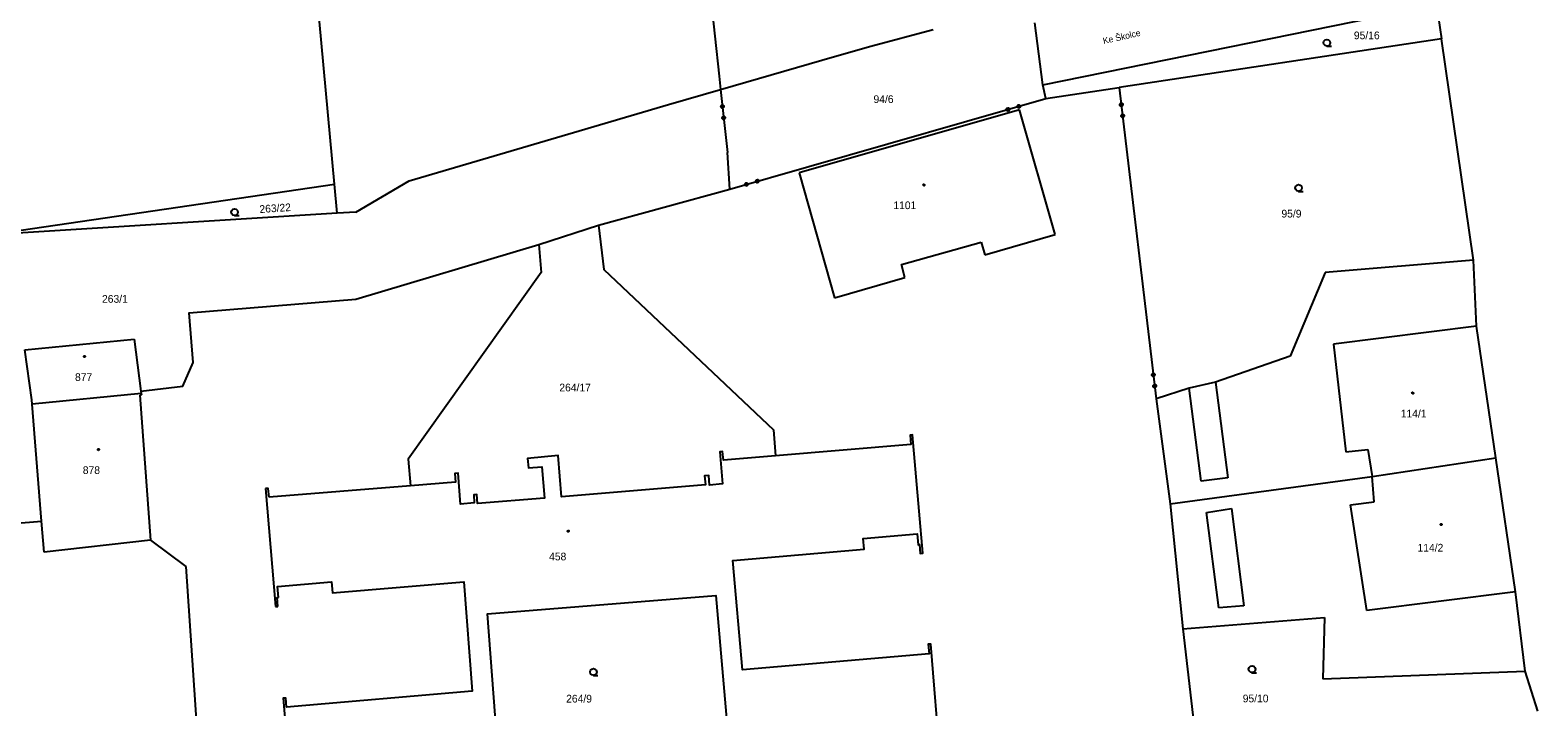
# Model space of a CAD drawing. Extents: x -757994 to -755874, y -1047691 to -1046119.
# Drawn here: x -757261.1 to -757094.8, y -1047292 to -1047217.4 of the extents above; entities that cross this region are included whole.
import ezdxf

# ---------------------------------------------------------------- set-up
doc = ezdxf.new("R2010")
doc.units = 0
doc.layers.add('katastrální mapa', color=7, linetype='Continuous')

msp = doc.modelspace()

# ---------------------------------------------------------------- linework, layer by layer
at = {"layer": 'katastrální mapa'}
for p, q in [((-757227.56, -1047234.43), (-757234.45, -1047159.9)), ((-757190.76, -1047170.38), (-757185.13, -1047222.5)), ((-757149.43, -1047223.45), (-757105.99, -1047214.66)), ((-757105.99, -1047214.66), (-757105.45, -1047218.39)), ((-757168.4, -1047219.21), (-757161.51, -1047217.36)), ((-757149.43, -1047223.45), (-757150.29, -1047216.64)), ((-757172.4, -1047220.36), (-757168.4, -1047219.21)), ((-757105.45, -1047218.39), (-757140.99, -1047223.76)), ((-757101.91, -1047242.8), (-757105.45, -1047218.39)), ((-757184.97, -1047223.97), (-757172.4, -1047220.36)), ((-757185.13, -1047222.5), (-757184.97, -1047223.97)), ((-757190.72, -1047225.62), (-757184.97, -1047223.97)), ((-757184.97, -1047223.97), (-757184.22, -1047230.92)), ((-757149.1, -1047224.98), (-757149.43, -1047223.45)), ((-757149.1, -1047224.98), (-757140.99, -1047223.76)), ((-757140.99, -1047223.76), (-757136.93, -1047258.08)), ((-757201.81, -1047228.89), (-757190.72, -1047225.62)), ((-757183.95, -1047234.96), (-757149.1, -1047224.98)), ((-757151.99, -1047226.23), (-757176.31, -1047233.17)), ((-757148.05, -1047239.97), (-757151.99, -1047226.23)), ((-757219.33, -1047234.05), (-757201.81, -1047228.89)), ((-757183.95, -1047234.96), (-757184.22, -1047230.92)), ((-757225.19, -1047237.5), (-757219.33, -1047234.05)), ((-757176.31, -1047233.17), (-757172.39, -1047246.93)), ((-757265.74, -1047240.02), (-757227.56, -1047234.43)), ((-757227.26, -1047237.63), (-757227.56, -1047234.43)), ((-757198.44, -1047238.94), (-757183.95, -1047234.96)), ((-757227.26, -1047237.63), (-757265.74, -1047240.02)), ((-757225.19, -1047237.5), (-757227.26, -1047237.63)), ((-757205.02, -1047241.08), (-757198.44, -1047238.94)), ((-757165.03, -1047243.26), (-757156.24, -1047240.8)), ((-757156.24, -1047240.8), (-757155.81, -1047242.21)), ((-757155.81, -1047242.21), (-757148.05, -1047239.97)), ((-757164.63, -1047244.7), (-757165.03, -1047243.26)), ((-757118.27, -1047244.15), (-757122.16, -1047253.39)), ((-757101.91, -1047242.8), (-757118.27, -1047244.15)), ((-757101.58, -1047250.06), (-757101.91, -1047242.8)), ((-757172.39, -1047246.93), (-757164.63, -1047244.7)), ((-757101.58, -1047250.06), (-757117.37, -1047252.05)), ((-757099.46, -1047264.58), (-757101.58, -1047250.06)), ((-757261.69, -1047252.67), (-757249.65, -1047251.49)), ((-757260.92, -1047258.21), (-757261.69, -1047252.67)), ((-757249.65, -1047251.49), (-757248.9, -1047257.23)), ((-757117.37, -1047252.05), (-757116.02, -1047263.94)), ((-757122.16, -1047253.39), (-757130.39, -1047256.24)), ((-757248.87, -1047257.48), (-757260.88, -1047258.66)), ((-757248.84, -1047257.65), (-757249.01, -1047257.68)), ((-757248.9, -1047257.23), (-757248.87, -1047257.48)), ((-757248.87, -1047257.48), (-757248.84, -1047257.65)), ((-757133.28, -1047256.92), (-757136.93, -1047258.08)), ((-757130.39, -1047256.24), (-757133.28, -1047256.92)), ((-757131.98, -1047267.15), (-757133.28, -1047256.92)), ((-757130.39, -1047256.24), (-757129.03, -1047266.78)), ((-757260.88, -1047258.66), (-757260.92, -1047258.21)), ((-757259.88, -1047271.57), (-757260.88, -1047258.66)), ((-757249.01, -1047257.68), (-757247.85, -1047273.65)), ((-757136.93, -1047258.08), (-757135.38, -1047269.65)), ((-757116.02, -1047263.94), (-757113.59, -1047263.68)), ((-757113.59, -1047263.68), (-757113.09, -1047266.64)), ((-757113.09, -1047266.64), (-757099.46, -1047264.58)), ((-757097.28, -1047279.34), (-757099.46, -1047264.58)), ((-757135.38, -1047269.65), (-757113.09, -1047266.64)), ((-757129.03, -1047266.78), (-757131.98, -1047267.15)), ((-757112.89, -1047269.42), (-757113.09, -1047266.64)), ((-757235.17, -1047267.98), (-757234.07, -1047280.98)), ((-757219.18, -1047267.68), (-757234.77, -1047268.94)), ((-757135.38, -1047269.65), (-757133.98, -1047283.45)), ((-757131.38, -1047270.62), (-757128.63, -1047270.17)), ((-757130.02, -1047281.14), (-757131.38, -1047270.62)), ((-757128.63, -1047270.17), (-757127.27, -1047280.89)), ((-757115.48, -1047269.76), (-757112.89, -1047269.42)), ((-757113.68, -1047281.4), (-757115.48, -1047269.76)), ((-757262.98, -1047271.83), (-757259.88, -1047271.57)), ((-757259.57, -1047274.97), (-757259.88, -1047271.57)), ((-757247.85, -1047273.65), (-757259.57, -1047274.97)), ((-757247.85, -1047273.65), (-757243.94, -1047276.55)), ((-757243.94, -1047276.55), (-757242.75, -1047294.55)), ((-757127.27, -1047280.89), (-757130.02, -1047281.14)), ((-757097.28, -1047279.34), (-757113.68, -1047281.4)), ((-757096.23, -1047288.12), (-757097.28, -1047279.34)), ((-757234.07, -1047280.98), (-757233.79, -1047280.96)), ((-757133.98, -1047283.45), (-757118.36, -1047282.19)), ((-757118.36, -1047282.19), (-757118.56, -1047288.96)), ((-757133.98, -1047283.45), (-757132.41, -1047297.02)), ((-757118.56, -1047288.96), (-757096.23, -1047288.12)), ((-757094.83, -1047292.5), (-757096.23, -1047288.12))]:
    msp.add_line(p, q, dxfattribs=at)
for points in [[(-757118.09, -1047219.19), (-757118.28, -1047219.14), (-757118.42, -1047219), (-757118.47, -1047218.82), (-757118.42, -1047218.64), (-757118.28, -1047218.5), (-757118.1, -1047218.45), (-757117.91, -1047218.5), (-757117.77, -1047218.64), (-757117.73, -1047218.83), (-757117.77, -1047219.01), (-757117.91, -1047219.15), (-757118.1, -1047219.2), (-757117.6, -1047219.2)], [(-757184.6, -1047225.91), (-757184.68, -1047226.01), (-757184.82, -1047226.03), (-757184.92, -1047225.94), (-757184.94, -1047225.81), (-757184.85, -1047225.7), (-757184.72, -1047225.69), (-757184.61, -1047225.77), (-757184.6, -1047225.91), (-757184.62, -1047225.9), (-757184.63, -1047225.78), (-757184.68, -1047225.75), (-757184.66, -1047225.95), (-757184.69, -1047225.99), (-757184.72, -1047225.71), (-757184.76, -1047225.72), (-757184.73, -1047226), (-757184.77, -1047226), (-757184.8, -1047225.72), (-757184.84, -1047225.73), (-757184.81, -1047226), (-757184.85, -1047225.97), (-757184.88, -1047225.77), (-757184.91, -1047225.81), (-757184.9, -1047225.93)], [(-757153.26, -1047226.01), (-757153.15, -1047226.07), (-757153.11, -1047226.2), (-757153.17, -1047226.32), (-757153.3, -1047226.36), (-757153.42, -1047226.29), (-757153.46, -1047226.16), (-757153.39, -1047226.04), (-757153.26, -1047226.01), (-757153.26, -1047226.03), (-757153.38, -1047226.06), (-757153.41, -1047226.11), (-757153.21, -1047226.05), (-757153.16, -1047226.08), (-757153.43, -1047226.16), (-757153.42, -1047226.2), (-757153.15, -1047226.12), (-757153.14, -1047226.16), (-757153.41, -1047226.24), (-757153.4, -1047226.27), (-757153.13, -1047226.2), (-757153.16, -1047226.25), (-757153.35, -1047226.3), (-757153.3, -1047226.33), (-757153.19, -1047226.3)], [(-757152.06, -1047225.66), (-757151.95, -1047225.73), (-757151.91, -1047225.86), (-757151.97, -1047225.97), (-757152.1, -1047226.01), (-757152.22, -1047225.95), (-757152.26, -1047225.82), (-757152.19, -1047225.7), (-757152.06, -1047225.66), (-757152.07, -1047225.69), (-757152.19, -1047225.72), (-757152.21, -1047225.77), (-757152.02, -1047225.71), (-757151.97, -1047225.74), (-757152.24, -1047225.82), (-757152.23, -1047225.86), (-757151.96, -1047225.78), (-757151.95, -1047225.82), (-757152.22, -1047225.89), (-757152.21, -1047225.93), (-757151.94, -1047225.86), (-757151.97, -1047225.9), (-757152.16, -1047225.96), (-757152.11, -1047225.99), (-757151.99, -1047225.95)], [(-757140.6, -1047225.69), (-757140.68, -1047225.8), (-757140.82, -1047225.81), (-757140.92, -1047225.73), (-757140.94, -1047225.6), (-757140.86, -1047225.49), (-757140.72, -1047225.48), (-757140.62, -1047225.56), (-757140.6, -1047225.69), (-757140.62, -1047225.69), (-757140.63, -1047225.57), (-757140.68, -1047225.54), (-757140.66, -1047225.73), (-757140.69, -1047225.78), (-757140.72, -1047225.5), (-757140.76, -1047225.51), (-757140.73, -1047225.78), (-757140.77, -1047225.79), (-757140.8, -1047225.51), (-757140.84, -1047225.51), (-757140.81, -1047225.79), (-757140.85, -1047225.76), (-757140.88, -1047225.56), (-757140.91, -1047225.6), (-757140.9, -1047225.72)], [(-757184.47, -1047227.15), (-757184.55, -1047227.25), (-757184.68, -1047227.27), (-757184.79, -1047227.18), (-757184.8, -1047227.05), (-757184.72, -1047226.95), (-757184.59, -1047226.93), (-757184.48, -1047227.02), (-757184.47, -1047227.15), (-757184.49, -1047227.14), (-757184.5, -1047227.02), (-757184.54, -1047226.98), (-757184.52, -1047227.18), (-757184.56, -1047227.22), (-757184.59, -1047226.95), (-757184.63, -1047226.95), (-757184.6, -1047227.23), (-757184.64, -1047227.23), (-757184.67, -1047226.95), (-757184.71, -1047226.96), (-757184.68, -1047227.24), (-757184.72, -1047227.2), (-757184.74, -1047227), (-757184.78, -1047227.05), (-757184.77, -1047227.17)], [(-757140.45, -1047226.93), (-757140.54, -1047227.04), (-757140.67, -1047227.06), (-757140.78, -1047226.97), (-757140.79, -1047226.84), (-757140.71, -1047226.73), (-757140.57, -1047226.72), (-757140.47, -1047226.8), (-757140.45, -1047226.93), (-757140.48, -1047226.92), (-757140.49, -1047226.8), (-757140.53, -1047226.77), (-757140.51, -1047226.97), (-757140.55, -1047227.01), (-757140.58, -1047226.73), (-757140.62, -1047226.74), (-757140.58, -1047227.02), (-757140.62, -1047227.02), (-757140.66, -1047226.74), (-757140.7, -1047226.75), (-757140.66, -1047227.02), (-757140.71, -1047226.99), (-757140.73, -1047226.79), (-757140.77, -1047226.84), (-757140.75, -1047226.95)], [(-757182.1, -1047234.27), (-757181.99, -1047234.33), (-757181.95, -1047234.46), (-757182.02, -1047234.58), (-757182.15, -1047234.61), (-757182.26, -1047234.55), (-757182.3, -1047234.42), (-757182.23, -1047234.3), (-757182.1, -1047234.27), (-757182.1, -1047234.29), (-757182.22, -1047234.32), (-757182.25, -1047234.37), (-757182.05, -1047234.31), (-757182.01, -1047234.34), (-757182.27, -1047234.42), (-757182.26, -1047234.46), (-757181.99, -1047234.38), (-757181.98, -1047234.42), (-757182.25, -1047234.49), (-757182.24, -1047234.53), (-757181.97, -1047234.46), (-757182, -1047234.51), (-757182.19, -1047234.56), (-757182.14, -1047234.59), (-757182.03, -1047234.56)], [(-757180.9, -1047233.92), (-757180.79, -1047233.99), (-757180.75, -1047234.12), (-757180.81, -1047234.23), (-757180.94, -1047234.27), (-757181.06, -1047234.21), (-757181.1, -1047234.08), (-757181.03, -1047233.96), (-757180.9, -1047233.92), (-757180.91, -1047233.94), (-757181.03, -1047233.98), (-757181.06, -1047234.03), (-757180.86, -1047233.97), (-757180.81, -1047234), (-757181.08, -1047234.08), (-757181.07, -1047234.11), (-757180.8, -1047234.04), (-757180.79, -1047234.08), (-757181.06, -1047234.15), (-757181.05, -1047234.19), (-757180.78, -1047234.11), (-757180.81, -1047234.16), (-757181, -1047234.22), (-757180.95, -1047234.25), (-757180.84, -1047234.21)], [(-757121.22, -1047235.2), (-757121.41, -1047235.15), (-757121.54, -1047235.01), (-757121.6, -1047234.83), (-757121.54, -1047234.65), (-757121.41, -1047234.51), (-757121.23, -1047234.46), (-757121.04, -1047234.51), (-757120.91, -1047234.65), (-757120.85, -1047234.84), (-757120.91, -1047235.02), (-757121.04, -1047235.16), (-757121.23, -1047235.21), (-757120.73, -1047235.21)], [(-757238.56, -1047237.87), (-757238.75, -1047237.82), (-757238.89, -1047237.69), (-757238.94, -1047237.5), (-757238.89, -1047237.32), (-757238.75, -1047237.18), (-757238.57, -1047237.13), (-757238.38, -1047237.18), (-757238.25, -1047237.32), (-757238.2, -1047237.51), (-757238.25, -1047237.7), (-757238.38, -1047237.83), (-757238.57, -1047237.88), (-757238.07, -1047237.88)], [(-757198.44, -1047238.94), (-757197.85, -1047243.83), (-757179.14, -1047261.49), (-757178.9, -1047264.37)], [(-757248.9, -1047257.23), (-757244.26, -1047256.69), (-757243.15, -1047254.07), (-757243.57, -1047248.6), (-757225.19, -1047247.1), (-757205.02, -1047241.08)], [(-757205.02, -1047241.08), (-757204.75, -1047244.16), (-757219.42, -1047264.72), (-757219.18, -1047267.68)], [(-757137.08, -1047255.48), (-757137.16, -1047255.59), (-757137.29, -1047255.61), (-757137.4, -1047255.52), (-757137.41, -1047255.39), (-757137.33, -1047255.28), (-757137.2, -1047255.27), (-757137.09, -1047255.35), (-757137.08, -1047255.48), (-757137.1, -1047255.48), (-757137.11, -1047255.36), (-757137.15, -1047255.33), (-757137.13, -1047255.53), (-757137.17, -1047255.57), (-757137.2, -1047255.29), (-757137.24, -1047255.3), (-757137.21, -1047255.58), (-757137.25, -1047255.58), (-757137.28, -1047255.3), (-757137.32, -1047255.31), (-757137.29, -1047255.59), (-757137.33, -1047255.55), (-757137.35, -1047255.35), (-757137.39, -1047255.4), (-757137.37, -1047255.52)], [(-757136.93, -1047256.73), (-757137.01, -1047256.83), (-757137.15, -1047256.85), (-757137.25, -1047256.76), (-757137.27, -1047256.63), (-757137.18, -1047256.52), (-757137.05, -1047256.51), (-757136.94, -1047256.59), (-757136.93, -1047256.73), (-757136.95, -1047256.71), (-757136.96, -1047256.59), (-757137.01, -1047256.56), (-757136.99, -1047256.76), (-757137.02, -1047256.8), (-757137.05, -1047256.52), (-757137.09, -1047256.53), (-757137.06, -1047256.81), (-757137.1, -1047256.81), (-757137.13, -1047256.53), (-757137.17, -1047256.54), (-757137.14, -1047256.82), (-757137.18, -1047256.78), (-757137.21, -1047256.58), (-757137.24, -1047256.63), (-757137.23, -1047256.75)], [(-757160.7, -1047298.2), (-757161.78, -1047285.11), (-757162.07, -1047285.13), (-757161.98, -1047286.2), (-757182.55, -1047287.95), (-757183.62, -1047275.92), (-757169.13, -1047274.66), (-757169.23, -1047273.47), (-757163.3, -1047272.96), (-757163.19, -1047274.16), (-757163.03, -1047274.15), (-757162.95, -1047275.13), (-757162.67, -1047275.11), (-757163.79, -1047262.06), (-757164.07, -1047262.08), (-757163.98, -1047263.12), (-757178.9, -1047264.37)], [(-757178.9, -1047264.37), (-757184.66, -1047264.85), (-757184.74, -1047263.89), (-757185.04, -1047263.91), (-757184.75, -1047267.47), (-757186.19, -1047267.59), (-757186.28, -1047266.53), (-757186.73, -1047266.57), (-757186.64, -1047267.56), (-757202.51, -1047268.87), (-757202.88, -1047264.34), (-757206.25, -1047264.65), (-757206.16, -1047265.7), (-757204.67, -1047265.57), (-757204.38, -1047269.02), (-757211.76, -1047269.63), (-757211.85, -1047268.64), (-757212.2, -1047268.67), (-757212.13, -1047269.55), (-757213.64, -1047269.68), (-757213.92, -1047266.27), (-757214.27, -1047266.3), (-757214.19, -1047267.28), (-757219.18, -1047267.68)], [(-757234.77, -1047268.94), (-757234.86, -1047267.95), (-757235.17, -1047267.98)], [(-757233.72, -1047279.98), (-757233.82, -1047278.77), (-757227.88, -1047278.27), (-757227.77, -1047279.47), (-757213.28, -1047278.24), (-757212.36, -1047290.32), (-757232.84, -1047292.07), (-757232.92, -1047291.07), (-757233.22, -1047291.09), (-757232.1, -1047304.05)], [(-757233.79, -1047280.96), (-757233.87, -1047279.99), (-757233.72, -1047279.98)], [(-757209.14, -1047302.17), (-757210.66, -1047281.8), (-757185.5, -1047279.75), (-757183.72, -1047300.09)], [(-757126.35, -1047288.26), (-757126.54, -1047288.21), (-757126.68, -1047288.08), (-757126.73, -1047287.89), (-757126.68, -1047287.71), (-757126.54, -1047287.57), (-757126.35, -1047287.52), (-757126.17, -1047287.57), (-757126.03, -1047287.71), (-757125.98, -1047287.9), (-757126.03, -1047288.09), (-757126.17, -1047288.22), (-757126.36, -1047288.27), (-757125.86, -1047288.27)], [(-757198.99, -1047288.56), (-757199.18, -1047288.51), (-757199.32, -1047288.38), (-757199.36, -1047288.19), (-757199.32, -1047288.01), (-757199.18, -1047287.87), (-757198.99, -1047287.82), (-757198.81, -1047287.87), (-757198.68, -1047288.01), (-757198.62, -1047288.2), (-757198.68, -1047288.39), (-757198.81, -1047288.52), (-757199, -1047288.57), (-757198.5, -1047288.57)]]:
    msp.add_lwpolyline(points, dxfattribs=at)
for points in [[(-757162.53, -1047234.43), (-757162.48, -1047234.44), (-757162.46, -1047234.48), (-757162.45, -1047234.51), (-757162.46, -1047234.56), (-757162.5, -1047234.59), (-757162.53, -1047234.6), (-757162.58, -1047234.58), (-757162.6, -1047234.55), (-757162.61, -1047234.51), (-757162.6, -1047234.47), (-757162.57, -1047234.43)], [(-757255.12, -1047253.33), (-757255.07, -1047253.34), (-757255.04, -1047253.38), (-757255.03, -1047253.41), (-757255.04, -1047253.46), (-757255.09, -1047253.49), (-757255.12, -1047253.5), (-757255.17, -1047253.48), (-757255.2, -1047253.45), (-757255.21, -1047253.41), (-757255.2, -1047253.37), (-757255.16, -1047253.33)], [(-757108.62, -1047257.36), (-757108.57, -1047257.37), (-757108.54, -1047257.41), (-757108.53, -1047257.44), (-757108.54, -1047257.48), (-757108.59, -1047257.52), (-757108.62, -1047257.52), (-757108.67, -1047257.51), (-757108.7, -1047257.48), (-757108.71, -1047257.44), (-757108.7, -1047257.4), (-757108.66, -1047257.36)], [(-757253.59, -1047263.59), (-757253.54, -1047263.6), (-757253.51, -1047263.64), (-757253.5, -1047263.67), (-757253.51, -1047263.72), (-757253.55, -1047263.75), (-757253.59, -1047263.76), (-757253.64, -1047263.74), (-757253.67, -1047263.71), (-757253.68, -1047263.67), (-757253.67, -1047263.62), (-757253.62, -1047263.59)], [(-757201.76, -1047272.58), (-757201.71, -1047272.59), (-757201.69, -1047272.63), (-757201.68, -1047272.66), (-757201.69, -1047272.71), (-757201.73, -1047272.74), (-757201.76, -1047272.75), (-757201.8, -1047272.73), (-757201.84, -1047272.7), (-757201.85, -1047272.66), (-757201.84, -1047272.62), (-757201.79, -1047272.58)], [(-757105.49, -1047271.85), (-757105.44, -1047271.86), (-757105.42, -1047271.9), (-757105.41, -1047271.93), (-757105.42, -1047271.98), (-757105.46, -1047272.01), (-757105.49, -1047272.02), (-757105.53, -1047272), (-757105.57, -1047271.97), (-757105.58, -1047271.93), (-757105.57, -1047271.89), (-757105.52, -1047271.85)]]:
    msp.add_lwpolyline(points, close=True, dxfattribs=at)

# ---------------------------------------------------------------- texts
for s, height, rotation, p in [('Ke Školce', 0.7, 12.8343, (-757142.71, -1047218.98)), ('263/22', 0.85, 3.7242, (-757235.8, -1047237.6))]:
    msp.add_text(s, height=height, rotation=rotation, dxfattribs=at).set_placement(p)
for s, p in [('95/16', (-757115.12, -1047218.44)), ('94/6', (-757168.1, -1047225.47)), ('1101', (-757165.91, -1047237.17)), ('95/9', (-757123.11, -1047238.09)), ('263/1', (-757253.19, -1047247.49)), ('877', (-757256.17, -1047256.11)), ('264/17', (-757202.75, -1047257.26)), ('114/1', (-757109.95, -1047260.13)), ('878', (-757255.31, -1047266.37)), ('114/2', (-757108.1, -1047274.92)), ('458', (-757203.88, -1047275.89)), ('264/9', (-757202, -1047291.56)), ('95/10', (-757127.38, -1047291.54))]:
    msp.add_text(s, height=0.85, dxfattribs=at).set_placement(p)

doc.saveas('drawing.dxf')
